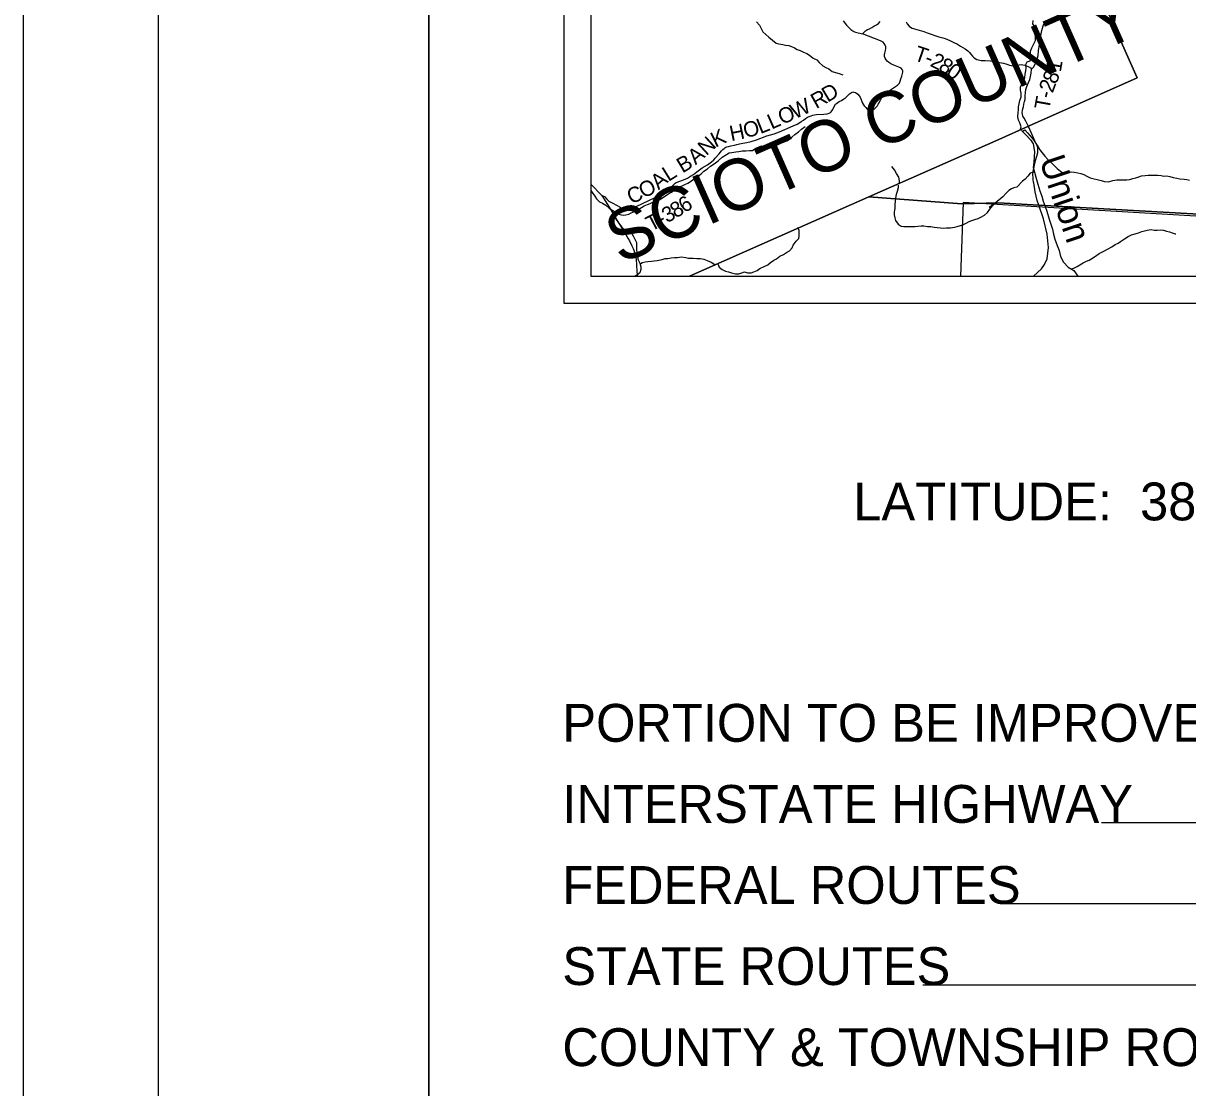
# Model space of a CAD drawing. Extents: x 0 to 82.7, y -0.2 to 22.
# Drawn here: x 0 to 4.308, y 11.097 to 15.035 of the extents above; entities that cross this region are included whole.
import ezdxf

# ---------------------------------------------------------------- set-up
doc = ezdxf.new("R2010")
doc.units = 0
for name, color, linetype in [('GM_X_County_Road', 7, 'Continuous'), ('GM_X_County_Text', 7, 'Continuous'), ('GM_X_Minor_River', 7, 'Continuous'), ('GM_X_Minor_River_Text', 7, 'Continuous'), ('GM_X_Township_Road', 7, 'Continuous'), ('GM_X_Township_Road_Text', 7, 'Continuous'), ('GM_X_Township_Text', 7, 'Continuous'), ('SH_Border', 7, 'Continuous'), ('SH_Cut_Line', 7, 'Continuous'), ('SH_Data', 7, 'Continuous'), ('SH_Text', 7, 'Continuous')]:
    doc.layers.add(name, color=color, linetype=linetype)

msp = doc.modelspace()

# ---------------------------------------------------------------- linework, layer by layer
at = {"layer": 'GM_X_County_Road'}
for points in [[(3.7381, 14.4463), (3.7362, 14.4581), (3.7354, 14.4808), (3.7456, 14.5274), (3.7534, 14.5555), (3.7541, 14.5616), (3.7542, 14.5718), (3.7521, 14.5792), (3.7475, 14.5886), (3.7189, 14.6538)], [(2.1, 14.4402), (2.1401, 14.3983), (2.1735, 14.3444), (2.1963, 14.307), (2.2246, 14.2621), (2.2374, 14.2399), (2.2432, 14.23), (2.2521, 14.212), (2.2566, 14.2023), (2.2598, 14.1922), (2.2628, 14.1831), (2.2655, 14.1727), (2.2671, 14.1624), (2.2695, 14.118), (2.2713, 14.1038), (2.2719, 14.1)], [(3.7373, 14.1), (3.7672, 14.127), (3.7784, 14.1424), (3.7886, 14.1635), (3.7938, 14.2055), (3.7888, 14.2546), (3.7745, 14.311), (3.7571, 14.3621), (3.7509, 14.38), (3.7435, 14.412), (3.7384, 14.4443), (3.7381, 14.4463)]]:
    msp.add_lwpolyline(points, dxfattribs=at)
msp.add_lwpolyline([(3.4675, 14.1), (4.5146, 14.1), (4.5265, 14.3104), (3.4778, 14.3723)], close=True, dxfattribs=at)
at = {"layer": 'GM_X_Minor_River'}
for points in [[(2.7133, 15.0411), (2.7238, 15.0277), (2.7316, 15.014), (2.7358, 15.0041), (2.7474, 14.9931), (2.7587, 14.9835), (2.7715, 14.9728), (2.785, 14.9617), (2.796, 14.9586), (2.8103, 14.9563), (2.8205, 14.9547), (2.833, 14.9535), (2.8428, 14.9492), (2.8537, 14.9439), (2.8635, 14.9381), (2.8749, 14.9339), (2.8862, 14.9289), (2.8994, 14.9239), (2.9092, 14.917), (2.9227, 14.9059), (2.9359, 14.8994), (2.9445, 14.8895), (2.9585, 14.878), (2.9694, 14.8711), (2.9807, 14.8665), (2.9931, 14.8573), (3.0056, 14.8531), (3.0184, 14.8496), (3.032, 14.8442)], [(3.6884, 14.6399), (3.6922, 14.6524), (3.687, 14.6665), (3.6825, 14.6764), (3.6792, 14.6896), (3.6805, 14.7052), (3.682, 14.7154), (3.6828, 14.7257), (3.6848, 14.7366), (3.6875, 14.7491), (3.6918, 14.7635), (3.6915, 14.7764), (3.6893, 14.7874), (3.6894, 14.8003), (3.6955, 14.8121), (3.7008, 14.8223), (3.7062, 14.8347), (3.707, 14.8469), (3.709, 14.859), (3.7102, 14.8692), (3.7091, 14.8825), (3.7149, 14.8927), (3.7255, 14.8961), (3.7301, 14.907), (3.7268, 14.9215), (3.7272, 14.9317), (3.7311, 14.9446), (3.7384, 14.9593), (3.7449, 14.9714), (3.7457, 14.9836), (3.7439, 14.9942), (3.7424, 15.0086), (3.7433, 15.0211), (3.7354, 15.0337), (3.7359, 15.0454)], [(2.3098, 14.3642), (2.3193, 14.3687), (2.3291, 14.3732), (2.339, 14.3773), (2.3523, 14.3825), (2.3652, 14.3896), (2.3773, 14.3983), (2.3876, 14.4039), (2.3978, 14.4107), (2.4077, 14.4178), (2.4255, 14.4295), (2.4373, 14.434), (2.4479, 14.4381), (2.4589, 14.4437), (2.4722, 14.4523), (2.4821, 14.4602), (2.4953, 14.4678), (2.5083, 14.4787), (2.5185, 14.4877), (2.5318, 14.4967), (2.5429, 14.5062), (2.5561, 14.5152), (2.571, 14.5268), (2.5858, 14.5397), (2.6017, 14.5502), (2.6112, 14.5554), (2.6222, 14.5569), (2.6362, 14.5594), (2.6472, 14.5609), (2.6601, 14.5627), (2.6737, 14.5634), (2.6865, 14.5641), (2.6979, 14.5644), (2.71, 14.573), (2.7222, 14.5783), (2.7316, 14.5813), (2.7445, 14.5793), (2.76, 14.5769), (2.7698, 14.5799), (2.7808, 14.5828), (2.7906, 14.5851), (2.8009, 14.5899), (2.8126, 14.5952), (2.8252, 14.6008), (2.8346, 14.6064), (2.8441, 14.6143), (2.8548, 14.6241), (2.8681, 14.6335), (2.8799, 14.6437), (2.8932, 14.6535)], [(3.693, 14.6379), (3.7134, 14.6193), (3.7279, 14.6033), (3.737, 14.5894), (3.7415, 14.5605), (3.7399, 14.5411), (3.7391, 14.5206), (3.7365, 14.502), (3.741, 14.4841), (3.7462, 14.4655), (3.7533, 14.4404), (3.7616, 14.4156), (3.7684, 14.3959), (3.7733, 14.3772), (3.7812, 14.3567), (3.7872, 14.3396), (3.7962, 14.3099), (3.8015, 14.2913), (3.8075, 14.2738), (3.812, 14.2544), (3.8168, 14.2365), (3.8251, 14.2129), (3.833, 14.1943), (3.8375, 14.1718), (3.8488, 14.1517), (3.8666, 14.1322), (3.887, 14.1208), (3.9014, 14.1)], [(3.6963, 14.6348), (3.706, 14.6412), (3.7154, 14.6301), (3.7244, 14.6199), (3.7331, 14.6096), (3.7403, 14.6001), (3.7463, 14.5906), (3.7546, 14.5777), (3.761, 14.567), (3.7697, 14.5556), (3.7795, 14.5438), (3.7908, 14.5316), (3.8029, 14.5202), (3.8154, 14.5073), (3.8252, 14.4974), (3.838, 14.4875), (3.8509, 14.4776), (3.8641, 14.4821), (3.8766, 14.4854), (3.8883, 14.4839), (3.9016, 14.4816), (3.9133, 14.4792), (3.9243, 14.4758), (3.9356, 14.4693), (3.9469, 14.4639), (3.9568, 14.4605), (3.978, 14.4559), (3.9882, 14.4532), (4.0007, 14.4493), (4.0147, 14.4489), (4.0317, 14.453), (4.0465, 14.456), (4.0593, 14.4563), (4.0836, 14.4562), (4.0941, 14.457), (4.1048, 14.4611), (4.1165, 14.4637), (4.1275, 14.4671), (4.1373, 14.4708), (4.151, 14.4715), (4.1616, 14.4734), (4.1733, 14.4737), (4.1835, 14.4733), (4.1979, 14.4729), (4.2096, 14.4717), (4.2198, 14.4698), (4.2316, 14.4705), (4.2425, 14.4682), (4.2543, 14.4643), (4.2675, 14.462), (4.2796, 14.4601), (4.2951, 14.4585), (4.3053, 14.4569), (4.3155, 14.4543)], [(3.2417, 14.4422), (3.2425, 14.4526), (3.2392, 14.4655), (3.2309, 14.4789), (3.2234, 14.4933), (3.2141, 14.5055)], [(3.741, 14.4841), (3.7256, 14.4811), (3.7172, 14.4697), (3.7066, 14.4588), (3.6968, 14.4512), (3.6763, 14.4285), (3.6653, 14.4267), (3.6558, 14.4229), (3.6463, 14.4169), (3.6353, 14.4052), (3.6243, 14.3931), (3.5953, 14.3701), (3.5951, 14.3719)], [(3.2373, 14.4361), (3.2366, 14.4262), (3.2327, 14.4129), (3.23, 14.4012), (3.2273, 14.3875), (3.2258, 14.3773), (3.225, 14.364), (3.2242, 14.3504), (3.2226, 14.3379), (3.2218, 14.3261), (3.2241, 14.3155), (3.2274, 14.3052), (3.2369, 14.2923), (3.2486, 14.2843), (3.2584, 14.2827), (3.2716, 14.2835), (3.2883, 14.2838), (3.2981, 14.2838), (3.3095, 14.2845), (3.3219, 14.2856), (3.3325, 14.2852), (3.3458, 14.2836), (3.3575, 14.2832), (3.37, 14.2805), (3.3817, 14.2793), (3.3942, 14.2778), (3.4051, 14.2774), (3.4161, 14.2781), (3.4305, 14.2788), (3.4449, 14.2803), (3.4558, 14.2833), (3.4676, 14.2871), (3.4782, 14.2912), (3.4892, 14.2961), (3.5002, 14.3014), (3.5096, 14.3055), (3.5202, 14.3093), (3.5331, 14.313), (3.5429, 14.3176), (3.557, 14.3255), (3.5672, 14.3353), (3.5763, 14.3478), (3.5855, 14.3599), (3.5953, 14.3701), (3.5733, 14.3539)], [(2.1, 14.4159), (2.1051, 14.4087), (2.1145, 14.3953), (2.1208, 14.385), (2.1318, 14.3751), (2.1431, 14.369), (2.1551, 14.3621), (2.1683, 14.351), (2.1815, 14.343), (2.1931, 14.3349), (2.2071, 14.3272), (2.2192, 14.3253), (2.229, 14.3264), (2.24, 14.3289), (2.2495, 14.3342), (2.262, 14.3387), (2.2741, 14.3454), (2.2874, 14.3533), (2.2973, 14.3597), (2.3098, 14.3642)], [(2.1753, 14.3467), (2.1784, 14.3384), (2.1829, 14.3281), (2.1877, 14.3183), (2.1967, 14.3049), (2.2147, 14.2805), (2.2256, 14.2695), (2.2374, 14.2675), (2.2498, 14.2599), (2.2573, 14.2458), (2.2644, 14.2336), (2.2688, 14.2237), (2.2691, 14.2104), (2.2691, 14.1979), (2.2701, 14.1861), (2.2723, 14.1763), (2.2738, 14.1626), (2.2812, 14.1478), (2.2853, 14.1345), (2.2853, 14.1242), (2.281, 14.1113), (2.27, 14.1034), (2.264, 14.1)], [(2.5697, 14.1454), (2.5752, 14.1325), (2.5862, 14.1245), (2.5982, 14.118), (2.6088, 14.116), (2.6201, 14.1118), (2.6349, 14.1083), (2.647, 14.1086), (2.6587, 14.112), (2.6682, 14.1153), (2.6799, 14.1115), (2.6935, 14.1118), (2.703, 14.1159), (2.7151, 14.12), (2.7257, 14.1276), (2.7409, 14.1358), (2.7542, 14.1418), (2.7641, 14.1498), (2.777, 14.1584), (2.7868, 14.1641), (2.7994, 14.1731), (2.8126, 14.1802), (2.8233, 14.1874), (2.8354, 14.1938), (2.8445, 14.2047), (2.8487, 14.2146), (2.859, 14.2286), (2.8689, 14.2384), (2.8708, 14.2478), (2.8713, 14.2577), (2.8706, 14.2683), (2.8657, 14.2801)], [(3.8766, 14.1266), (3.8871, 14.1285), (3.8988, 14.1357), (3.9087, 14.1417), (3.9215, 14.1489), (3.9337, 14.1545), (3.9435, 14.1587), (3.9541, 14.1651), (3.967, 14.1737), (3.981, 14.1832), (3.9981, 14.1918), (4.0277, 14.2077), (4.0402, 14.2163), (4.0504, 14.222), (4.0599, 14.2276), (4.0739, 14.2371), (4.0876, 14.2457), (4.1001, 14.2518), (4.1137, 14.2563), (4.1258, 14.2604), (4.1383, 14.2653), (4.1489, 14.2675), (4.1588, 14.2694), (4.1728, 14.2716), (4.1845, 14.27), (4.1955, 14.27), (4.2087, 14.2703), (4.2186, 14.2699), (4.2299, 14.2661), (4.2405, 14.2638), (4.2503, 14.2596), (4.2617, 14.2565), (4.2643, 14.2561)], [(2.2825, 14.1435), (2.2903, 14.1504), (2.3006, 14.1522), (2.3104, 14.154), (2.3248, 14.1555), (2.3346, 14.1562), (2.3448, 14.158), (2.3638, 14.1617), (2.3751, 14.1643), (2.385, 14.165), (2.3971, 14.1672), (2.4092, 14.1686), (2.4201, 14.1689), (2.4353, 14.1707), (2.4515, 14.1684), (2.4617, 14.166), (2.4784, 14.1659), (2.4916, 14.1651), (2.506, 14.1646), (2.5181, 14.1627), (2.5301, 14.158), (2.5456, 14.1507), (2.5554, 14.145), (2.5601, 14.1411)]]:
    msp.add_lwpolyline(points, dxfattribs=at)
at = {"layer": 'GM_X_Township_Road'}
for points in [[(3.0338, 15.0446), (3.0453, 15.0288), (3.0571, 15.0165), (3.0619, 15.0118), (3.0726, 15.0046), (3.0797, 15.0023), (3.1056, 14.9963)], [(3.1056, 14.9963), (3.1096, 15.0013), (3.1159, 15.007), (3.1234, 15.0116), (3.1314, 15.0151), (3.1399, 15.0191), (3.1438, 15.0219), (3.147, 15.0242), (3.1565, 15.03), (3.1644, 15.0347), (3.1704, 15.0415)], [(3.2665, 15.0403), (3.2709, 15.0335), (3.2772, 15.025), (3.2826, 15.0213), (3.2889, 15.0177), (3.3228, 15.0073), (3.332, 15.0043), (3.3447, 15.0001), (3.3588, 14.9951), (3.3724, 14.9902), (3.3877, 14.9856), (3.4019, 14.9819), (3.4106, 14.9785), (3.4282, 14.9718), (3.4425, 14.9643), (3.4561, 14.9579), (3.4682, 14.9508), (3.4854, 14.9409), (3.4947, 14.9334), (3.5005, 14.9275), (3.5064, 14.9205), (3.5117, 14.9136), (3.5161, 14.9095), (3.5214, 14.9045), (3.5276, 14.9015), (3.5343, 14.8996), (3.5436, 14.8978), (3.5588, 14.897), (3.5792, 14.896), (3.5879, 14.8946), (3.596, 14.8932), (3.602, 14.8914), (3.6125, 14.8895), (3.6196, 14.8887), (3.6269, 14.8873), (3.6358, 14.8847), (3.6422, 14.8825), (3.6487, 14.8806), (3.6558, 14.8784), (3.6614, 14.8772), (3.6671, 14.877), (3.673, 14.878), (3.6782, 14.8798), (3.6851, 14.8817), (3.6918, 14.8821), (3.6978, 14.8817), (3.7061, 14.8796), (3.7174, 14.8752), (3.7263, 14.8701), (3.7298, 14.8655)], [(3.7189, 14.6538), (3.7136, 14.6654), (3.7089, 14.673), (3.7027, 14.6838), (3.6988, 14.6914), (3.697, 14.6987), (3.6964, 14.7048), (3.6968, 14.7119), (3.6982, 14.7181), (3.7003, 14.7266), (3.7023, 14.7361), (3.7049, 14.7456), (3.7065, 14.7535), (3.7075, 14.767), (3.7079, 14.779), (3.7098, 14.7905), (3.7132, 14.8018), (3.7195, 14.8164), (3.7243, 14.8273), (3.7271, 14.8382), (3.7286, 14.8511), (3.7298, 14.8655), (3.7346, 14.8691), (3.7374, 14.8726), (3.7443, 14.8835), (3.7484, 14.8938), (3.7514, 14.9023), (3.7546, 14.916), (3.7564, 14.9336), (3.7597, 14.957), (3.7631, 14.9843), (3.7655, 14.9967), (3.7684, 15.0086), (3.7736, 15.0254), (3.7805, 15.0413)], [(2.1401, 14.3983), (2.1499, 14.3941), (2.1595, 14.3846), (2.1671, 14.3771), (2.1814, 14.369), (2.2083, 14.3545), (2.2137, 14.351), (2.2192, 14.3482), (2.2236, 14.3464), (2.2271, 14.3452), (2.2317, 14.3436), (2.2362, 14.3438), (2.2414, 14.3448), (2.2678, 14.3567), (2.3384, 14.39), (2.3767, 14.4115), (2.3878, 14.4202), (2.4064, 14.4382), (2.4114, 14.4432), (2.4161, 14.4466), (2.4332, 14.4519), (2.4484, 14.458), (2.4581, 14.4624), (2.4684, 14.4689), (2.4792, 14.4758), (2.4919, 14.4853), (2.5022, 14.4931), (2.5115, 14.4998), (2.5319, 14.5113), (2.5467, 14.5225), (2.5547, 14.5297), (2.5602, 14.5358), (2.5751, 14.5524), (2.5834, 14.5633), (2.5881, 14.5683), (2.5929, 14.5724), (2.5958, 14.5746), (2.5988, 14.5762), (2.6028, 14.578), (2.6091, 14.5797), (2.6174, 14.5817), (2.6309, 14.5841), (2.6396, 14.5863), (2.6495, 14.5888), (2.6619, 14.5916), (2.6768, 14.5946), (2.6928, 14.598), (2.7128, 14.6045), (2.7506, 14.6185), (2.7779, 14.6266), (2.7981, 14.634), (2.849, 14.6553), (2.8628, 14.6619), (2.8695, 14.6652), (2.878, 14.6712), (2.8868, 14.6769), (2.8939, 14.6825), (2.902, 14.6872), (2.9075, 14.69), (2.9154, 14.6929), (2.9208, 14.6947), (2.9277, 14.6967), (2.9346, 14.6975), (2.9624, 14.6989), (2.9744, 14.7005), (2.9817, 14.702), (2.9861, 14.7046), (2.9897, 14.7078), (2.9948, 14.7163), (3.0005, 14.7272), (3.0055, 14.7365), (3.0091, 14.7389), (3.0193, 14.7456), (3.0269, 14.7497), (3.0363, 14.7556), (3.0403, 14.7585), (3.0443, 14.7622), (3.049, 14.7662), (3.057, 14.7745), (3.0639, 14.779), (3.069, 14.781), (3.0728, 14.7802), (3.0787, 14.779), (3.0833, 14.7767), (3.0878, 14.7727), (3.0932, 14.7668), (3.0961, 14.7616), (3.0993, 14.7551), (3.1023, 14.7452), (3.1048, 14.7395), (3.1086, 14.7331), (3.1112, 14.7294), (3.1137, 14.7268), (3.1171, 14.723), (3.1219, 14.7179), (3.1274, 14.7147), (3.1324, 14.7123), (3.1381, 14.7123), (3.1436, 14.7146), (3.1478, 14.7171), (3.1535, 14.7224), (3.1589, 14.7284), (3.1636, 14.7359), (3.1668, 14.7413), (3.1725, 14.7541), (3.1761, 14.7606), (3.1787, 14.764), (3.1816, 14.7685), (3.1862, 14.7737), (3.2197, 14.7964), (3.2313, 14.804), (3.2341, 14.8067), (3.2378, 14.8099), (3.2414, 14.8132), (3.2432, 14.817), (3.2446, 14.8212), (3.2469, 14.8297), (3.2507, 14.8398), (3.2539, 14.854), (3.2543, 14.859), (3.2523, 14.8645), (3.2479, 14.8687), (3.2392, 14.8732), (3.2208, 14.8804), (3.2101, 14.8853), (3.202, 14.8905), (3.1963, 14.8954), (3.1921, 14.8998), (3.1892, 14.9056), (3.1868, 14.9124), (3.186, 14.9182), (3.1872, 14.9245), (3.1905, 14.9348), (3.1919, 14.9417), (3.1913, 14.9494), (3.1895, 14.9548), (3.1858, 14.9603), (3.181, 14.9655), (3.1761, 14.9682), (3.1717, 14.9708), (3.1276, 14.9878), (3.1056, 14.9963)]]:
    msp.add_lwpolyline(points, dxfattribs=at)
at = {"layer": 'GM_X_Township_Text'}
msp.add_lwpolyline([(3.8036, 15.5496), (4.1209, 14.8338), (3.7187, 14.6543), (3.6092, 14.6054), (3.1288, 14.3932), (3.472, 14.3677), (3.6086, 14.371), (3.7569, 14.3626), (5.5319, 14.2622), (6.4714, 14.2058), (6.5437, 14.2015), (6.8262, 14.1829), (7.3099, 14.151), (7.7427, 14.1224), (8.0832, 14.1), (8.9, 14.1), (8.9, 20.1381)], dxfattribs=at)
for points in [[(2.1, 19.5964), (2.1, 14.1), (2.4652, 14.1), (3.1288, 14.3932), (3.6092, 14.6054), (3.7187, 14.6543), (4.1209, 14.8338), (3.8036, 15.5496), (3.6125, 15.9807), (3.4071, 16.476), (3.2909, 16.7562), (3.0556, 17.2782), (3.0279, 17.3486), (2.7199, 18.1299), (2.4438, 18.782), (2.397, 18.8926), (2.3145, 19.0873), (2.2742, 19.1826)], [(2.4652, 14.1), (6.5387, 14.1), (6.5437, 14.2015), (6.4714, 14.2058), (5.5319, 14.2622), (3.7569, 14.3626), (3.6086, 14.371), (3.472, 14.3677), (3.1288, 14.3932)]]:
    msp.add_lwpolyline(points, close=True, dxfattribs=at)
at = {"layer": 'SH_Border'}
for points in [[(0.5, 21.5), (1.5, 21.5), (1.5, 0.5), (0.5, 0.5)], [(1.5, 21.5), (33.5, 21.5), (33.5, 0.5), (1.5, 0.5)]]:
    msp.add_lwpolyline(points, close=True, dxfattribs=at)
at = {"layer": 'SH_Cut_Line'}
msp.add_lwpolyline([(0, 0), (34, 0), (34, 22), (0, 22)], close=True, dxfattribs=at)
for points in [[(2.1, 20.9), (2.1, 14.1), (2.4652, 14.1), (3.1288, 14.3932), (3.6092, 14.6054), (3.7187, 14.6543), (4.1209, 14.8338), (3.8036, 15.5496)], [(3.8036, 15.5496), (4.1209, 14.8338), (3.7187, 14.6543), (3.6092, 14.6054), (3.1288, 14.3932), (2.4652, 14.1), (8.9, 14.1), (8.9, 20.9)]]:
    msp.add_lwpolyline(points, dxfattribs=at)
at = {"layer": 'SH_Data'}
for p, q in [((2, 21), (2, 14)), ((2.1, 20.9), (2.1, 14.1)), ((2.1, 14.1), (8.9, 14.1)), ((2.1, 14.1), (2.1, 14.1)), ((2, 14), (9, 14)), ((7.7, 12.0767), (3.9895, 12.0767)), ((7.7, 11.7767), (3.6192, 11.7767)), ((7.7, 11.4767), (3.3288, 11.4767))]:
    msp.add_line(p, q, dxfattribs=at)

# ---------------------------------------------------------------- texts
at = {"layer": 'GM_X_County_Text'}
msp.add_text('SCIOTO COUNTY', height=0.189394, rotation=23.8999, dxfattribs=at).set_placement((2.2092, 14.142))
at = {"layer": 'GM_X_Minor_River_Text'}
msp.add_text('Union', height=0.09469, rotation=288.4935, dxfattribs=at).set_placement((3.7585, 14.5289))
at = {"layer": 'GM_X_Township_Road_Text'}
for s, rotation, p in [('T', 341.1029, (3.2917, 14.8999)), ('-', 338.6226, (3.3313, 14.8864)), ('2', 333.8818, (3.3519, 14.8784)), ('8', 328.8662, (3.3822, 14.8636)), ('0', 325.3162, (3.4114, 14.846)), ('1', 80.0746, (3.8386, 14.8529)), ('2', 69.7266, (3.8087, 14.7747)), ('8', 66.6039, (3.8206, 14.8068)), ('R', 29.3165, (2.9338, 14.7173)), ('D', 30.7679, (2.9758, 14.741)), ('-', 75.8606, (3.8035, 14.7536)), ('W', 24.8931, (2.8542, 14.6794)), ('T', 79.9631, (3.7963, 14.7128)), ('L', 23.8218, (2.7686, 14.6415)), ('O', 23.8947, (2.8075, 14.6587)), ('H', 11.5811, (2.6193, 14.5986)), ('O', 15.0931, (2.6719, 14.6095)), ('L', 21.81, (2.7271, 14.6249)), ('N', 42.4353, (2.5274, 14.5431)), ('K', 25.8336, (2.5607, 14.5744)), ('A', 40.3896, (2.4876, 14.5093)), ('B', 30.6783, (2.4389, 14.4793)), ('A', 40.3179, (2.3506, 14.4168)), ('L', 32.0358, (2.3869, 14.4478)), ('O', 28.3673, (2.2959, 14.3857)), ('C', 23.8917, (2.2489, 14.3647)), ('6', 32.7871, (2.4464, 14.3315)), ('3', 28.7022, (2.3816, 14.2949)), ('8', 30.0519, (2.4136, 14.3125)), ('T', 27.8512, (2.3226, 14.2637)), ('-', 28.0516, (2.3604, 14.2836))]:
    msp.add_text(s, height=0.0568, rotation=rotation, dxfattribs=at).set_placement(p)
at = {"layer": 'SH_Text'}
for s, p in [('LATITUDE:  38°40\'28"     LONGITUDE:  -82°41\'33"', (3.071, 13.1959)), ('PORTION TO BE IMPROVED', (1.9944, 12.3767)), ('INTERSTATE HIGHWAY', (1.9944, 12.0767)), ('FEDERAL ROUTES', (1.9944, 11.7767)), ('STATE ROUTES', (1.9944, 11.4767)), ('COUNTY & TOWNSHIP ROADS', (1.9944, 11.1767))]:
    msp.add_text(s, height=0.14, dxfattribs=at).set_placement(p)

doc.saveas('drawing.dxf')
